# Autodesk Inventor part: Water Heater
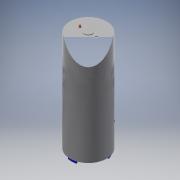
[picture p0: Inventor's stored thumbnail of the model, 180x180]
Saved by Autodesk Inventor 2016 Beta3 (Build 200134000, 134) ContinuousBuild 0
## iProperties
flow_configuration: 1
height: 0 in
loss_method: 0
radius: 2.500 in
shape: 1 ul
width: 0 in
allow_slope_adjustment: 0
flow_configuration2: 1
flow_direction: 2
radius: 0.500 in
shape: 0 ul
Created: 2006-02
Part Number: Water Heater
Document SubType Name: Modeling
Designer: Autodesk, Inc.
Description: BODY - WATER HEATER, 45 GAL
Mass: 2.9406e+06 g
Surface Area: 32761.1 cm^2
Volume: 374598 cm^3
Density: 7.85 g/cm^3
Material: Galvanized Steel
Appearance: Steel
Title: BODY - WATER HEATER, 45 GAL
Author: Autodesk, Inc.
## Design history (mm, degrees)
sketch "Sketch1"
  geometry: C1 r 279.4 at (0, 0)
  constraints: 1 centre point
  dimensions: "d0" = 558.8 diameter of C1
extrude "Extrusion1" new body sketch "Sketch1" distance "d1" = 1524; taper "d2" = 0 deg
workplane "Work Plane2"
sketch "Sketch2"
  geometry: C1 r 241.3 at (0, 0); C2 r 63.5 at (0, 0); C3 r 279.4 at (0, 0) reference
  constraints: 2 centre point, 1 coincident
  dimensions: "d4" = 127 diameter of C2
extrude "Extrusion2" join sketch "Sketch2" distance "d5" = 9.525; taper "d6" = 0 deg
workplane "Work Plane1"
sketch "Sketch3"
  geometry: C1 r 241.3 at (0, 0); C2 r 18.528 at (-127, 0); C3 r 18.528 at (127, 0); C4 r 63.5 at (0, 0) reference; C5 r 279.4 at (0, 0) reference
  constraints: 3 centre point, 2 horizontal alignment, 1 equal radius
  dimensions: "d8" = 127 distance of C2.centre C1.centre; "d9" = 254 distance of C2.centre C3.centre (= 2 x d8); "d10" = 37.05617 diameter of C2
extrude "Extrusion3" cut sketch "Sketch3" distance "d11" = 9.525; taper "d12" = 0 deg
workplane "Work Plane3"
sketch "Sketch4"
  geometry: C1 r 15.875 at (0, 1340.887)
  constraints: 1 centre point
  dimensions: "d13" = 31.75 diameter of C1
extrude "Extrusion4" cut sketch "Sketch4" distance "d14" = 9.525; taper "d15" = 0 deg
sketch "Sketch5"
  geometry: C1 r 18.528 at (0, 0) reference; C2 r 12.7 at (0, 0); 1 further point
  constraints: 1 centre point, 1 coincident
  dimensions: "d16" = 25.4 diameter of C2
extrude "Extrusion5" new body sketch "Sketch5" distance "d17" = 34.925; taper "d18" = 0 deg
pattern_linear "Rectangular Pattern1" dims "d21" = 254
sketch "Sketch6"
  geometry: L1 (0, 0)-(0, 262.412); L2 (60.612, 226.208)-(65.543, 244.609); L3 (-60.612, 226.208)-(-65.543, 244.609); C1 r 279.4 at (0, 0) reference; A1 r 234.188 centre (0, 0) between (60.612, 226.208) and (-60.612, 226.208); A2 r 253.238 centre (0, 0) between (65.543, 244.609) and (-65.543, 244.609)
  constraints: 6 end point, 4 point on circle, 2 centre point, 2 coincident, 2 point on line, 1 vertical
  dimensions: "d22" = 30 deg angle of L2 L3; "d23" = 15 deg angle of L2 L1; "d24" = 19.05 radial gap between concentric circles of A2 A1; "d25" = 468.376 diameter of A1
extrude "Extrusion6" new body sketch "Sketch6" distance "d26" = 50.8; taper "d27" = 0 deg
pattern_circular "Circular Pattern1" dims angle "d29" = 360 deg
sketch "Sketch7"
  geometry: C1 r 15.875 at (0, 0) reference; C2 r 12.7 at (0, 0); 1 further point
  constraints: 1 centre point, 1 coincident
  dimensions: "d31" = 25.4 diameter of C2
extrude "Extrusion7" new body sketch "Sketch7" distance "d32" = 34.925; taper "d33" = 0 deg
workplane "Work Plane4"
sketch "Sketch8"
  geometry: L1 (-38.1, 279.4)-(38.1, 279.4); L2 (38.1, 279.4)-(38.1, 203.2); L3 (-38.1, 203.2)-(-38.1, 279.4); L4 (-279.4, 0)-(279.4, 0) reference; L5 (38.1, 203.2)-(14.028, 203.2); L6 (-14.028, 203.2)-(-38.1, 203.2); L7 (0, -55.88)-(0, 335.28) reference; A1 r 19.355 centre (0, 216.535) between (-14.028, 203.2) and (14.028, 203.2); 3 further points
  constraints: 10 end point, 3 parallel, 2 point on circle, 1 centre point, 1 coincident, 1 collinear, 1 horizontal, 1 perpendicular, 1 point on line, 1 vertical alignment
  dimensions: "d35" = 76.2 distance between parallel lines of L2 L3; "d36" = 76.2 distance of L3.start L1.start; "d37" = 38.1 distance from line of L2 point (0, 241.3); "d39" = 241.3 distance from line of L4 point (0, 241.3); "d40" = 24.765 distance of point (0, 241.3) point (0, 216.535); "d41" = 38.7096 diameter of A1; "d42" = 38.1 distance from line of L6 point (0, 241.3)
extrude "Extrusion8" new body sketch "Sketch8" distance "d43" = 50.8; taper "d44" = 0 deg
sketch "Sketch9"
  geometry: L1 (0, 76.2)-(0, 0) reference; L2 (0, 76.2)-(-50.8, 76.2) reference; C1 r 12.7 at (-25.4, 38.1); 2 further points
  constraints: 1 centre point, 1 coincident
  dimensions: "d45" = 25.4 diameter of C1; "d46" = 38.1 distance from line of L2 point (-25.4, 38.1); "d47" = 25.4 distance from line of L1 point (-25.4, 38.1)
extrude "Extrusion9" new body sketch "Sketch9" distance "d48" = 50.8; taper "d49" = 0 deg
body "Solid1"
body "Solid2"
feature "Pattern of Solid2:1"
body "Solid3"
body "Solid4"
body "Solid5"
body "Solid6"
body "Solid7"
other parameters: "d34" = -330.2, "d38" = 38.1
